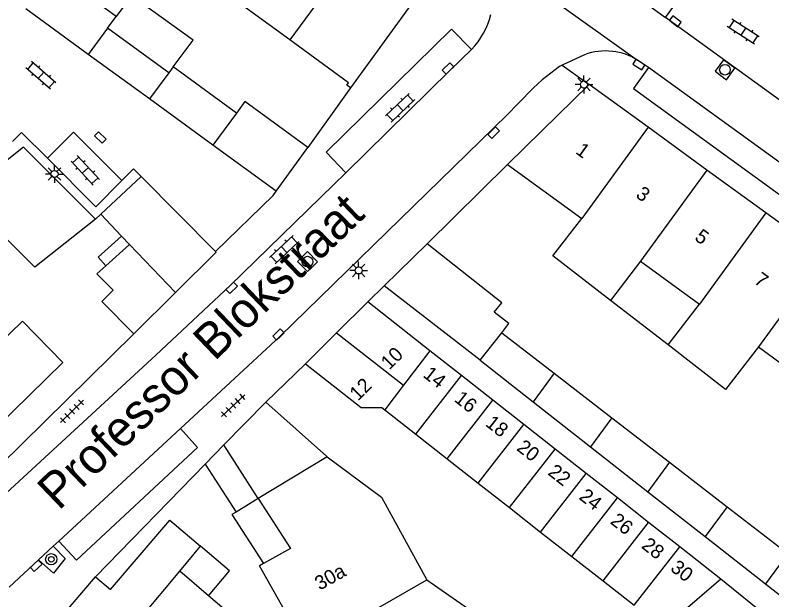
# Model space of a CAD drawing. Extents: x 132999 to 136000, y 398499 to 400501.
# Drawn here: x 134109.3 to 134162.7, y 398536.9 to 398578.2 of the extents above; entities that cross this region are included whole.
import ezdxf

# ---------------------------------------------------------------- set-up
doc = ezdxf.new("R2010")
doc.units = 0
for name, color, linetype in [('gg-afsc-hekwerk', 7, 'Continuous'), ('gg-afsc-muur', 7, 'Continuous'), ('gg-anno-huisnummerreeks BGT', 7, 'Continuous'), ('gg-anno-openbare ruimte label', 7, 'Continuous'), ('gg-bbg-bijgebouw', 7, 'Continuous'), ('gg-bbg-gedigitaliseerde bebouwing', 7, 'Continuous'), ('gg-bbg-gedigitaliseerde bijgebouw', 7, 'Continuous'), ('gg-bbg-hoofdgebouw', 7, 'Continuous'), ('gg-bbg-luifel en loopbrug', 7, 'Continuous'), ('gg-bbg-tussenscheiding', 7, 'Continuous'), ('gg-knt-verharding', 7, 'Continuous'), ('gg-knt-verharding nz', 7, 'Continuous'), ('gt-grn-weggrens', 7, 'Continuous'), ('gt-symb-boom', 7, 'Continuous'), ('gt-symb-klinker verharding', 7, 'Continuous'), ('gt-symb-kolk', 7, 'Continuous'), ('gt-symb-kolk center center', 7, 'Continuous'), ('gt-symb-lichtmast', 7, 'Continuous'), ('gt-symb-rioolschacht', 7, 'Continuous'), ('gt-symb-tegel verharding', 7, 'Continuous')]:
    doc.layers.add(name, color=color, linetype=linetype)

# ---------------------------------------------------------------- blocks, each defined once
blk = doc.blocks.new('gt0-KOLK')
at = {"layer": 'gt-symb-kolk'}
blk.add_lwpolyline([(0, 0), (0.375, 0), (0.375, 0.4), (-0.375, 0.4), (-0.375, 0), (0, 0)], dxfattribs=at)
blk = doc.blocks.new('gt0-KL1')
at = {"layer": 'gt-symb-klinker verharding'}
for p, q in [((-1.15, 0.3), (1.15, 0.3)), ((-1, -0.3), (-1, 0.3)), ((-0.5, 0.3), (-0.5, 0.45)), ((0, -0.3), (0, 0.3)), ((0.5, 0.3), (0.5, 0.45)), ((1, -0.3), (1, 0.3)), ((-1.15, -0.3), (1.15, -0.3)), ((-0.5, -0.45), (-0.5, -0.3)), ((0.5, -0.45), (0.5, -0.3))]:
    blk.add_line(p, q, dxfattribs=at)
blk = doc.blocks.new('gt0-LMAST')
at = {"layer": 'gt-symb-lichtmast'}
for p, q in [((-0.005, 0.246), (-0.005, 0.621)), ((-0.182, 0.173), (-0.447, 0.438)), ((0.172, 0.173), (0.437, 0.438)), ((-0.255, -0.004), (-0.63, -0.004)), ((-0.182, -0.181), (-0.447, -0.446)), ((-0.005, -0.254), (-0.005, -0.629)), ((0.437, -0.446), (0.172, -0.181)), ((0.245, -0.004), (0.62, -0.004))]:
    blk.add_line(p, q, dxfattribs=at)
blk.add_circle((-0.005, -0.004), 0.25, dxfattribs=at)
blk = doc.blocks.new('gt0-RS')
at = {"layer": 'gt-symb-rioolschacht'}
blk.add_lwpolyline([(-0.5, -0.5), (0.5, -0.5), (0.5, 0.5), (-0.5, 0.5)], close=True, dxfattribs=at)
blk.add_circle((0, 0), 0.375, dxfattribs=at)
blk = doc.blocks.new('gt0-TEG1')
at = {"layer": 'gt-symb-tegel verharding'}
for p, q in [((-1.125, 0), (1.125, 0)), ((-0.9, -0.25), (-0.9, 0.25)), ((-0.45, -0.25), (-0.45, 0.25)), ((0, -0.25), (0, 0.25)), ((0.45, -0.25), (0.45, 0.25)), ((0.9, -0.25), (0.9, 0.25))]:
    blk.add_line(p, q, dxfattribs=at)
blk = doc.blocks.new('gt0-KOLKCC')
at = {"layer": 'gt-symb-kolk center center'}
blk.add_lwpolyline([(-0.375, 0.2), (0.375, 0.2), (0.375, -0.2), (-0.375, -0.2)], close=True, dxfattribs=at)
blk = doc.blocks.new('gt0-BOOM')
at = {"layer": 'gt-symb-boom'}
for radius in [0.4, 0.2]:
    blk.add_circle((0, 0), radius, dxfattribs=at)

msp = doc.modelspace()

# ---------------------------------------------------------------- linework, layer by layer
at = {"layer": 'gg-afsc-hekwerk'}
msp.add_line((134126.97, 398550.83), (134129.75, 398553.54), dxfattribs=at)
at = {"layer": 'gg-afsc-muur'}
for p, q in [((134132.94, 398573.033), (134129.923, 398568.802)), ((134144.031, 398567.61), (134138.35, 398562.01)), ((134115.295, 398564.096), (134114.939, 398563.764)), ((134108.19, 398546.36), (134117.63, 398555.66)), ((134114.93, 398538.52), (134122.681, 398546.477))]:
    msp.add_line(p, q, dxfattribs=at)
at = {"layer": 'gg-bbg-bijgebouw'}
for p, q in [((134114.416, 398575.381), (134110.016, 398578.593)), ((134118.733, 398572.249), (134114.416, 398575.381)), ((134123.226, 398568.97), (134118.733, 398572.249)), ((134127.677, 398565.722), (134123.226, 398568.97)), ((134129.5, 398568.222), (134129.923, 398568.802)), ((134127.677, 398565.722), (134129.5, 398568.222)), ((134118.164, 398566.771), (134115.295, 398564.096)), ((134118.164, 398566.771), (134123.408, 398561.466)), ((134138.35, 398562.01), (134135.32, 398559.04)), ((134123.457, 398561.416), (134120.586, 398558.579)), ((134123.408, 398561.466), (134123.457, 398561.416)), ((134120.586, 398558.579), (134117.63, 398555.66)), ((134131.96, 398555.725), (134134.17, 398557.91)), ((134129.75, 398553.54), (134131.96, 398555.725)), ((134126.97, 398550.83), (134123.99, 398547.82))]:
    msp.add_line(p, q, dxfattribs=at)
msp.add_lwpolyline([(134114.939, 398563.764), (134109.857, 398568.836), (134105.559, 398565.449)], dxfattribs=at)
at = {"layer": 'gg-bbg-gedigitaliseerde bebouwing'}
for p, q in [((134144.031, 398567.61), (134149.27, 398563.803)), ((134153.427, 398560.782), (134151.294, 398558.018)), ((134153.427, 398560.782), (134157.585, 398557.761)), ((134155.361, 398554.879), (134157.585, 398557.761)), ((134103.757, 398550.713), (134109.766, 398556.553)), ((134112.62, 398553.63), (134109.766, 398556.553)), ((134161.742, 398554.739), (134165.899, 398551.718)), ((134131.235, 398547.039), (134131.296, 398546.993)), ((134131.296, 398546.993), (134135.13, 398544.135)), ((134135.13, 398544.135), (134138.329, 398538.301)), ((134120.18, 398542.52), (134122.349, 398540.678)), ((134120.878, 398538.912), (134122.349, 398540.678)), ((134126.792, 398539.45), (134126.523, 398539.299)), ((134129.824, 398533.424), (134126.523, 398539.299)), ((134122.914, 398537.18), (134120.878, 398538.912))]:
    msp.add_line(p, q, dxfattribs=at)
for points in [[(134151.294, 398558.018), (134147.227, 398561.157), (134149.27, 398563.803)], [(134161.742, 398554.739), (134159.428, 398551.74), (134155.361, 398554.879)], [(134126.429, 398544.038), (134128.698, 398540.521), (134126.792, 398539.45)], [(134117.501, 398525.11), (134125.732, 398534.782), (134122.914, 398537.18)]]:
    msp.add_lwpolyline(points, dxfattribs=at)
at = {"layer": 'gg-bbg-gedigitaliseerde bijgebouw'}
for p, q in [((134115.776, 398577.236), (134116.381, 398578.062)), ((134120.114, 398574.089), (134115.776, 398577.236)), ((134124.886, 398571.245), (134120.424, 398574.501)), ((134116.773, 398562.555), (134115.295, 398564.096)), ((134117.332, 398561.972), (134116.773, 398562.555)), ((134117.332, 398561.972), (134115.66, 398560.462)), ((134142.087, 398553.801), (134135.32, 398559.04)), ((134138.546, 398554.474), (134134.17, 398557.91)), ((134143.616, 398555.739), (134147.325, 398552.876)), ((134140.787, 398552.715), (134138.546, 398554.474)), ((134142.087, 398553.801), (134145.849, 398550.856)), ((134147.325, 398552.876), (134151.392, 398549.737)), ((134142.988, 398550.988), (134140.787, 398552.715)), ((134126.97, 398550.83), (134131.235, 398547.039)), ((134145.188, 398549.261), (134142.988, 398550.988)), ((134145.849, 398550.856), (134149.895, 398547.688)), ((134135.353, 398550.293), (134137.554, 398548.572)), ((134151.392, 398549.737), (134155.459, 398546.599)), ((134147.388, 398547.533), (134145.188, 398549.261)), ((134137.554, 398548.572), (134139.757, 398546.848)), ((134126.429, 398544.038), (134123.99, 398547.82)), ((134149.588, 398545.806), (134147.388, 398547.533)), ((134149.895, 398547.688), (134153.94, 398544.52)), ((134139.757, 398546.848), (134141.96, 398545.125)), ((134155.459, 398546.599), (134159.526, 398543.46)), ((134151.788, 398544.079), (134149.588, 398545.806)), ((134141.96, 398545.125), (134144.164, 398543.401)), ((134153.94, 398544.52), (134157.985, 398541.353)), ((134153.989, 398542.352), (134151.788, 398544.079)), ((134144.164, 398543.401), (134146.366, 398541.678)), ((134159.526, 398543.46), (134163.812, 398540.152)), ((134156.189, 398540.624), (134153.989, 398542.352)), ((134146.366, 398541.678), (134148.57, 398539.954)), ((134157.985, 398541.353), (134162.25, 398538.014)), ((134159.085, 398538.351), (134156.189, 398540.624)), ((134148.57, 398539.954), (134150.773, 398538.23)), ((134150.773, 398538.23), (134152.976, 398536.507)), ((134162.57, 398535.541), (134159.085, 398538.351)), ((134162.25, 398538.014), (134166.298, 398534.844))]:
    msp.add_line(p, q, dxfattribs=at)
for points in [[(134116.381, 398578.062), (134111.984, 398581.271), (134111.702, 398580.888)], [(134120.424, 398574.501), (134120.423, 398574.501), (134120.114, 398574.089)], [(134129.923, 398568.802), (134125.473, 398572.049), (134124.886, 398571.245)], [(134114.939, 398563.764), (134110.641, 398560.377), (134105.559, 398565.449)], [(134143.616, 398555.739), (134144.126, 398556.385), (134143.095, 398557.199), (134143.614, 398557.857), (134138.35, 398562.01)], [(134115.66, 398560.462), (134115.033, 398559.896), (134116.174, 398558.741), (134115.371, 398557.947), (134117.63, 398555.66)], [(134129.75, 398553.54), (134133.69, 398550.47), (134135.141, 398550.459), (134135.353, 398550.293)], [(134138.329, 398538.301), (134144.154, 398534.251), (134147.944, 398529.466)]]:
    msp.add_lwpolyline(points, dxfattribs=at)
at = {"layer": 'gg-bbg-hoofdgebouw'}
for p, q in [((134128.653, 398576.408), (134124.26, 398579.613)), ((134137.749, 398579.651), (134132.94, 398573.033)), ((134149.79, 398573.26), (134146.46, 398569.993)), ((134153.947, 398570.239), (134149.79, 398573.26)), ((134146.46, 398569.993), (134144.031, 398567.61)), ((134158.105, 398567.218), (134153.947, 398570.239)), ((134162.262, 398564.197), (134158.105, 398567.218)), ((134166.419, 398561.176), (134162.262, 398564.197)), ((134109.37, 398532.03), (134114.93, 398538.52))]:
    msp.add_line(p, q, dxfattribs=at)
for points in [[(134132.94, 398573.033), (134132.678, 398573.21), (134132.796, 398573.384), (134128.653, 398576.408)], [(134108.19, 398546.36), (134106.72, 398547.87), (134112.62, 398553.63)], [(134114.93, 398538.52), (134115.99, 398537.61), (134120.18, 398542.52)]]:
    msp.add_lwpolyline(points, dxfattribs=at)
at = {"layer": 'gg-bbg-luifel en loopbrug'}
for p, q in [((134155.361, 398554.879), (134151.294, 398558.018)), ((134122.681, 398546.477), (134123.99, 398547.82)), ((134122.681, 398546.477), (134124.866, 398543.089)), ((134126.429, 398544.038), (134124.866, 398543.089))]:
    msp.add_line(p, q, dxfattribs=at)
for points in [[(134120.424, 398574.501), (134121.83, 398576.375), (134117.465, 398579.541), (134116.381, 398578.062)], [(134116.773, 398562.555), (134115.119, 398561.062), (134115.66, 398560.462)], [(134124.866, 398543.089), (134124.563, 398542.905), (134126.792, 398539.45)], [(134122.914, 398537.18), (134124.404, 398538.929), (134122.349, 398540.678)]]:
    msp.add_lwpolyline(points, dxfattribs=at)
at = {"layer": 'gg-bbg-tussenscheiding'}
for p, q in [((134134.268, 398584.111), (134128.653, 398576.408)), ((134115.776, 398577.236), (134114.416, 398575.381)), ((134120.114, 398574.089), (134118.733, 398572.249)), ((134124.886, 398571.245), (134123.226, 398568.97)), ((134153.947, 398570.239), (134149.27, 398563.803)), ((134158.105, 398567.218), (134153.427, 398560.782)), ((134162.262, 398564.197), (134157.585, 398557.761)), ((134120.586, 398558.579), (134117.332, 398561.972)), ((134166.419, 398561.176), (134161.742, 398554.739)), ((134131.96, 398555.725), (134136.688, 398552.041)), ((134142.087, 398553.801), (134143.616, 398555.739)), ((134138.546, 398554.474), (134136.688, 398552.041)), ((134147.325, 398552.876), (134145.849, 398550.856)), ((134137.554, 398548.572), (134140.787, 398552.715)), ((134136.688, 398552.041), (134135.353, 398550.293)), ((134139.757, 398546.848), (134142.988, 398550.988)), ((134151.392, 398549.737), (134149.895, 398547.688)), ((134141.96, 398545.125), (134145.188, 398549.261)), ((134144.164, 398543.401), (134147.388, 398547.533)), ((134131.296, 398546.993), (134126.429, 398544.038)), ((134155.459, 398546.599), (134153.94, 398544.52)), ((134146.366, 398541.678), (134149.588, 398545.806)), ((134148.57, 398539.954), (134151.788, 398544.079)), ((134159.526, 398543.46), (134157.985, 398541.353)), ((134150.773, 398538.23), (134153.989, 398542.352)), ((134152.976, 398536.507), (134156.189, 398540.624)), ((134163.812, 398540.152), (134162.25, 398538.014)), ((134134.281, 398535.98), (134138.329, 398538.301)), ((134159.085, 398538.351), (134155.31, 398535.117))]:
    msp.add_line(p, q, dxfattribs=at)
msp.add_lwpolyline([(134112.699, 398529.197), (134118.143, 398535.628), (134120.878, 398538.912)], dxfattribs=at)
at = {"layer": 'gg-knt-verharding'}
for p, q in [((134155.189, 398577.987), (134156.274, 398579.477)), ((134171.717, 398565.983), (134155.189, 398577.987)), ((134141.488, 398575.721), (134140.067, 398577.151)), ((134149.468, 398575.359), (134147.88, 398574.617)), ((134153.993, 398574.46), (134153.21, 398574.978)), ((134144.776, 398571.91), (134143.992, 398571.109)), ((134132.615, 398567.023), (134131.742, 398566.174)), ((134107.59, 398543.472), (134119.191, 398554.169)), ((134110.907, 398539.714), (134111.939, 398540.675)), ((134111.939, 398540.675), (134112.333, 398541.042)), ((134108.839, 398537.788), (134110.907, 398539.714))]:
    msp.add_line(p, q, dxfattribs=at)
for points in [[(134140.067, 398577.151), (134131.221, 398568.478), (134132.615, 398567.023)], [(134147.88, 398574.617), (134147.702, 398574.534), (134146.467, 398573.581), (134145.862, 398573.021), (134144.776, 398571.91)], [(134153.993, 398574.46), (134152.923, 398572.984), (134195.354, 398542.188), (134196.43, 398543.649)], [(134120.937, 398548.993), (134127.95, 398555.48), (134143.992, 398571.109)], [(134131.742, 398566.174), (134124.414, 398559.047), (134119.191, 398554.169)], [(134123.408, 398561.466), (134127.482, 398565.413), (134127.677, 398565.722)], [(134120.937, 398548.993), (134122.135, 398547.638), (134113.582, 398539.685), (134112.333, 398541.042)], [(134111.939, 398540.675), (134112.799, 398539.801), (134111.972, 398538.779), (134110.907, 398539.714)]]:
    msp.add_lwpolyline(points, dxfattribs=at)
for centre, radius, start, end in [((134137.516, 398579.502), 5.484, 316.4133, 346.2231), ((134150.952, 398571.343), 4.281, 83.5287, 110.2764), ((134150.947, 398571.343), 4.282, 58.0991, 83.4704)]:
    msp.add_arc(centre, radius, start, end, dxfattribs=at)
at = {"layer": 'gg-knt-verharding nz'}
for p, q in [((134137.887, 398590.607), (134155.189, 398577.987)), ((134192.976, 398546.14), (134153.993, 398574.46)), ((134112.333, 398541.042), (134120.937, 398548.993))]:
    msp.add_line(p, q, dxfattribs=at)
for points in [[(134141.488, 398575.721), (134139.955, 398574.239), (134132.615, 398567.023)], [(134111.529, 398568.05), (134113.386, 398569.9), (134116.791, 398566.487)], [(134116.791, 398566.487), (134114.947, 398564.626), (134111.529, 398568.05)]]:
    msp.add_lwpolyline(points, dxfattribs=at)
at = {"layer": 'gt-grn-weggrens'}
for p, q in [((134140.843, 398583.858), (134153.21, 398574.978)), ((134147.88, 398574.617), (134149.79, 398573.26)), ((134135.32, 398559.04), (134134.17, 398557.91))]:
    msp.add_line(p, q, dxfattribs=at)
for points in [[(134111.529, 398568.05), (134109.705, 398569.878), (134109.057, 398569.231)], [(134118.164, 398566.771), (134117.613, 398567.317), (134116.791, 398566.487)]]:
    msp.add_lwpolyline(points, dxfattribs=at)

# ---------------------------------------------------------------- block references
at = {"layer": 'gt-symb-boom'}
msp.add_blockref('gt0-BOOM', (134111.81, 398539.753), dxfattribs=at)
at = {"layer": 'gt-symb-klinker verharding'}
for p, rotation in [((134160.675, 398576.986), 147.12021809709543), ((134111.074, 398573.899), 139.13759358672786), ((134136.443, 398571.619), 43.54158234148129), ((134114.21, 398567.201), 133.01389341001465), ((134128.253, 398561.608), 43.01389341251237)]:
    msp.add_blockref('gt0-KL1', p, dxfattribs=dict(at, rotation=rotation))
at = {"layer": 'gt-symb-kolk'}
for p, rotation in [((134155.758, 398577.562), -36.70953402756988), ((134139.955, 398574.239), 44.027604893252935), ((134153.414, 398574.835), 147.04099012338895), ((134142.905, 398569.997), -135.08104064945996), ((134124.414, 398559.047), -135.81035302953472), ((134127.992, 398555.469), 44.27067303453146), ((134110.607, 398539.436), -136.9861065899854)]:
    msp.add_blockref('gt0-KOLK', p, dxfattribs=dict(at, rotation=rotation))
at = {"layer": 'gt-symb-kolk center center', "rotation": -44.675840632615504}
msp.add_blockref('gt0-KOLKCC', (134115.272, 398569.519), dxfattribs=at)
at = {"layer": 'gt-symb-lichtmast'}
for p in [(134149.431, 398573.262), (134112.037, 398566.943), (134133.518, 398560.14)]:
    msp.add_blockref('gt0-LMAST', p, dxfattribs=at)
at = {"layer": 'gt-symb-rioolschacht'}
for p, rotation in [((134159.383, 398574.298), 53.33640753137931), ((134129.902, 398560.758), 134.67584063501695)]:
    msp.add_blockref('gt0-RS', p, dxfattribs=dict(at, rotation=rotation))
at = {"layer": 'gt-symb-tegel verharding'}
for p, rotation in [((134124.658, 398550.6), 43.013893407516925), ((134113.271, 398550.189), 44.59480322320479)]:
    msp.add_blockref('gt0-TEG1', p, dxfattribs=dict(at, rotation=rotation))

# ---------------------------------------------------------------- texts
at = {"layer": 'gg-anno-huisnummerreeks BGT'}
for s, rotation, p in [('1', 324, (134148.775, 398568.435)), ('3', 324, (134153.019, 398565.351)), ('5', 324, (134157.176, 398562.33)), ('7', 324, (134161.366, 398559.286)), ('10', 44.7, (134135.677, 398553.071)), ('14', 322, (134137.997, 398552.668)), ('12', 44.7, (134133.467, 398550.886)), ('16', 322, (134140.201, 398550.944)), ('18', 322, (134142.403, 398549.221)), ('20', 322, (134144.606, 398547.498)), ('22', 322, (134146.81, 398545.774)), ('24', 322, (134149.012, 398544.051)), ('26', 322, (134151.217, 398542.326)), ('28', 322, (134153.419, 398540.603)), ('30', 322, (134155.459, 398539.007)), ('30a', 29.3, (134130.767, 398537.533))]:
    msp.add_text(s, height=1, rotation=rotation, dxfattribs=at).set_placement(p)
at = {"layer": 'gg-anno-openbare ruimte label'}
msp.add_text('Professor Blokstraat', height=2.5, rotation=43.8, dxfattribs=at).set_placement((134112.33, 398543.14))

doc.saveas('drawing.dxf')
